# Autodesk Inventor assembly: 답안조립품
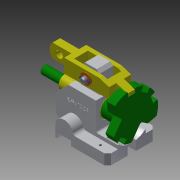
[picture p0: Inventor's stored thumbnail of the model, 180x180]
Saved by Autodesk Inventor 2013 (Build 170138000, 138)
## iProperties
Created: 2016-11
Part Number: 답안조립품
Document SubType Name: Assembly
Designer: 나래
Author: 나래
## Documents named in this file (8)
- C:\Users\나래\Desktop\461108V1024\답안조립품.iam
- C:\Users\나래\Desktop\461108V1024\본체.ipt
- C:\Users\나래\Desktop\461108V1024\부시.ipt
- C:\Users\나래\Desktop\461108V1024\분할대.ipt
- C:\Users\나래\Desktop\461108V1024\분할축.ipt
- C:\Users\나래\Desktop\461108V1024\와셔.ipt
- C:\Users\나래\Desktop\461108V1024\원통형핀.ipt
- C:\Users\나래\Desktop\461108V1024\클레비스핀.ipt
